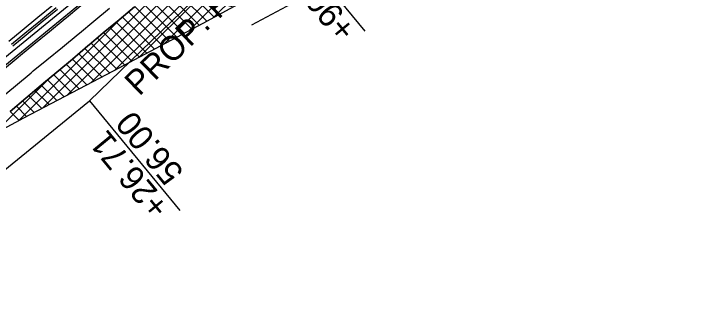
# Model space of a CAD drawing. Extents: x 1147550 to 1149124, y 2017436 to 2018779.
# Drawn here: x 1148734.8 to 1148907, y 2018257.9 to 2018327.9 of the extents above; entities that cross this region are included whole.
import ezdxf

# ---------------------------------------------------------------- set-up
doc = ezdxf.new("R2010")
doc.units = 0
for name, color, linetype in [('S_ELECTRIC_UTILITIES', 7, 'Continuous'), ('S_IRON_PIN_ANNOT', 7, 'Continuous'), ('S_MAILBOX', 7, 'Continuous'), ('S_SECONDARY_CTL', 7, 'Continuous'), ('S_TANK', 7, 'Continuous'), ('S_TELEPHONE_UTILITIES', 7, 'Continuous'), ('S_TELEPHONE_UTILITIES_ANNOT', 7, 'Continuous')]:
    doc.layers.add(name, color=color, linetype=linetype)

msp = doc.modelspace()

# ---------------------------------------------------------------- linework, layer by layer
at = {"layer": 'S_ELECTRIC_UTILITIES'}
for points in [[(1148799.03, 2018350.69), (1148821.27, 2018323.67)], [(1148753.45, 2018306.48), (1148775.68, 2018279.45)]]:
    msp.add_lwpolyline(points, dxfattribs=at)
at = {"layer": 'S_IRON_PIN_ANNOT'}
for p, q in [((1148784.04, 2018327.09), (1148856.95, 2018400.01)), ((1148777.91, 2018323.79), (1148849.77, 2018395.65)), ((1148771.86, 2018320.57), (1148842.58, 2018391.3)), ((1148765.8, 2018317.34), (1148830.54, 2018382.08)), ((1148759.75, 2018314.12), (1148818.22, 2018372.59)), ((1148753.78, 2018310.98), (1148805.84, 2018363.04)), ((1148747.82, 2018307.84), (1148791.81, 2018351.84)), ((1148741.85, 2018304.7), (1148777.05, 2018339.91)), ((1148772.38, 2018336.1), (1148782.33, 2018326.16)), ((1148773.94, 2018337.37), (1148784.16, 2018327.16)), ((1148770.82, 2018334.83), (1148780.49, 2018325.17)), ((1148769.26, 2018333.56), (1148778.64, 2018324.18)), ((1148766.15, 2018331.02), (1148774.95, 2018322.22)), ((1148767.7, 2018332.29), (1148776.8, 2018323.2)), ((1148764.61, 2018329.73), (1148773.11, 2018321.23)), ((1148763.08, 2018328.44), (1148771.26, 2018320.25)), ((1148735.86, 2018301.54), (1148761.07, 2018326.75)), ((1148760, 2018325.86), (1148767.57, 2018318.29)), ((1148761.54, 2018327.15), (1148769.42, 2018319.27)), ((1148758.44, 2018324.58), (1148765.73, 2018317.3)), ((1148756.89, 2018323.31), (1148763.88, 2018316.32)), ((1148753.84, 2018320.7), (1148760.19, 2018314.35)), ((1148755.37, 2018322), (1148762.03, 2018315.34)), ((1148752.31, 2018319.4), (1148758.34, 2018313.38)), ((1148750.78, 2018318.1), (1148756.49, 2018312.4)), ((1148747.71, 2018315.52), (1148752.78, 2018310.45)), ((1148749.25, 2018316.81), (1148754.63, 2018311.43)), ((1148746.17, 2018314.23), (1148750.92, 2018309.48)), ((1148729.8, 2018298.31), (1148743.42, 2018311.93)), ((1148744.63, 2018312.94), (1148749.07, 2018308.5)), ((1148741.55, 2018310.37), (1148745.36, 2018306.55)), ((1148743.09, 2018311.65), (1148747.22, 2018307.53)), ((1148740.01, 2018309.08), (1148743.51, 2018305.58)), ((1148738.47, 2018307.78), (1148741.66, 2018304.6)), ((1148735.42, 2018305.18), (1148737.95, 2018302.65)), ((1148736.94, 2018306.48), (1148739.8, 2018303.63)), ((1148733.9, 2018303.87), (1148736.1, 2018301.67))]:
    msp.add_line(p, q, dxfattribs=at)
for points in [[(1148725.05, 2018295.78), (1148737.29, 2018302.31), (1148759.39, 2018313.93), (1148781.46, 2018325.68), (1148803.37, 2018337.66), (1148825.28, 2018349.66), (1148846.98, 2018361.91), (1148869.23, 2018375.5), (1148890.45, 2018388.71), (1148911.17, 2018402.69), (1148932.43, 2018418.55), (1148951.91, 2018434.12), (1148970.58, 2018450.61), (1148989.32, 2018467.79), (1149007.56, 2018484.84), (1149025.52, 2018502.19), (1149043.36, 2018519.65), (1149061.14, 2018537.18), (1149078.8, 2018555.13), (1149096.46, 2018572.78), (1149114.15, 2018590.39), (1149117.96, 2018594.21)], [(1148764.53, 2018329.66), (1148760.71, 2018326.45), (1148756.85, 2018323.27), (1148753.35, 2018320.29), (1148753.04, 2018320.02), (1148749.23, 2018316.79), (1148745.39, 2018313.58), (1148742.1, 2018310.83), (1148741.56, 2018310.37), (1148737.73, 2018307.16), (1148733.93, 2018303.9)]]:
    msp.add_lwpolyline(points, dxfattribs=at)
at = {"layer": 'S_MAILBOX'}
msp.add_lwpolyline([(1147623.68, 2017436.42), (1147751.67, 2017548.43), (1147958.55, 2017704.02), (1148020.45, 2017753.36), (1148124.6, 2017828.73), (1148174.25, 2017853.51), (1148282.74, 2017941.53), (1148421.63, 2018031.39), (1148612.18, 2018197.22), (1148639.91, 2018214.06), (1148753.45, 2018306.48), (1148799.03, 2018350.69)], dxfattribs=at)
at = {"layer": 'S_SECONDARY_CTL'}
msp.add_lwpolyline([(1148733.93, 2018303.9), (1148737.73, 2018307.16), (1148741.56, 2018310.37), (1148742.1, 2018310.83), (1148745.39, 2018313.58), (1148749.23, 2018316.79), (1148753.04, 2018320.02), (1148753.35, 2018320.29), (1148756.85, 2018323.27), (1148760.71, 2018326.45), (1148764.53, 2018329.66)], dxfattribs=at)
at = {"layer": 'S_TANK'}
msp.add_line((1148793.41, 2018325.23), (1148804.51, 2018331.13), dxfattribs=at)
at = {"layer": 'S_TELEPHONE_UTILITIES'}
for points in [[(1148731.33, 2018307.06), (1148735.19, 2018310.24), (1148739.05, 2018313.41), (1148739.6, 2018313.87), (1148742.92, 2018316.59), (1148746.78, 2018319.77), (1148750.64, 2018322.94), (1148750.95, 2018323.2), (1148754.5, 2018326.12), (1148758.36, 2018329.3)], [(1148732.02, 2018314.1), (1148735.88, 2018317.28), (1148736.43, 2018317.73), (1148739.74, 2018320.45), (1148743.6, 2018323.63), (1148747.46, 2018326.81), (1148747.78, 2018327.07), (1148751.32, 2018329.98)], [(1148733.57, 2018321.2), (1148736.88, 2018323.93), (1148740.74, 2018327.1), (1148744.6, 2018330.28)], [(1148734.2, 2018320.43), (1148737.52, 2018323.16), (1148741.38, 2018326.33), (1148745.24, 2018329.51)], [(1148734.52, 2018320.04), (1148737.83, 2018322.77), (1148741.69, 2018325.95), (1148745.56, 2018329.12)]]:
    msp.add_lwpolyline(points, dxfattribs=at)
at = {"layer": 'S_TELEPHONE_UTILITIES_ANNOT'}
for p, q in [((1148642.87, 2018243.65), (1148860.75, 2018422.28)), ((1148642.87, 2018243.65), (1148860.75, 2018422.28)), ((1148643.82, 2018242.49), (1148861.7, 2018421.12)), ((1148643.82, 2018242.49), (1148861.7, 2018421.12))]:
    msp.add_line(p, q, dxfattribs=at)

# ---------------------------------------------------------------- texts
at = {"layer": 'S_ELECTRIC_UTILITIES'}
for s, p in [('+90.00', (1148819.48, 2018324.26)), ('56.00', (1148776.9, 2018288.99)), ('+26.71', (1148773.48, 2018280.56))]:
    msp.add_text(s, height=6, rotation=129.4453, dxfattribs=at).set_placement(p)
at = {"layer": 'S_MAILBOX'}
msp.add_text('PROP. R/W', height=6, rotation=44.1276, dxfattribs=at).set_placement((1148765.68, 2018307.48))

doc.saveas('drawing.dxf')
